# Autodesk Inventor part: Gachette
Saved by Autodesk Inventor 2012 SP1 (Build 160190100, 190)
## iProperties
Created: 2014-12
Part Number: Gachette
Material: Default
Document SubType Name: Modeling
Designer: Bruno
Density: 1 g/cm^3
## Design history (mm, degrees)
node "Gachette1"
node "Gachette"
node "Base1"
